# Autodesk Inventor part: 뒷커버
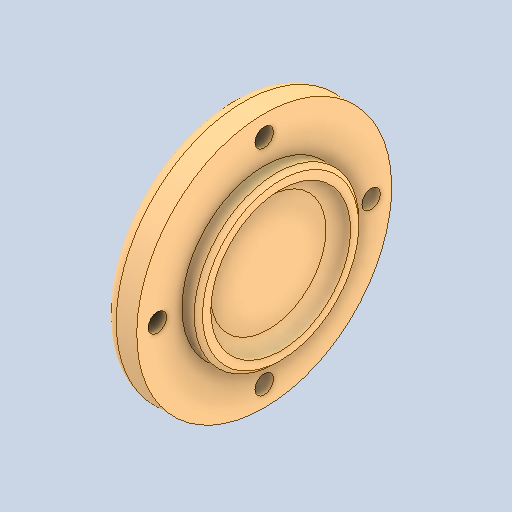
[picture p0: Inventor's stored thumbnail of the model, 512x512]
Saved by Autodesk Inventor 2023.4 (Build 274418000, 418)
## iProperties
Created: 2024-09
Part Number: 뒷커버
Material: 알루미늄 6061
Document SubType Name: Modeling
Designer: EDU
Density: 2.7 g/cm^3
Appearance: 기본값
Author: jhkim
Sending System: Autodesk Inventor 2025
Preprocessor: ST-DEVELOPER v20
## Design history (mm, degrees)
feature "솔리드1"
node "솔리드2"
